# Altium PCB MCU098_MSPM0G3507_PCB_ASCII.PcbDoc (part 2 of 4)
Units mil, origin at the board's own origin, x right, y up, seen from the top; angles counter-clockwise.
Board outline 2310.03 x 4205.03 mil, 4 copper layers (Top Layer, VCC Layer, GND Layer, Bottom Layer), stack 62.4 mil thick; 260 components, 182 nets, 835 pads, 237 vias.
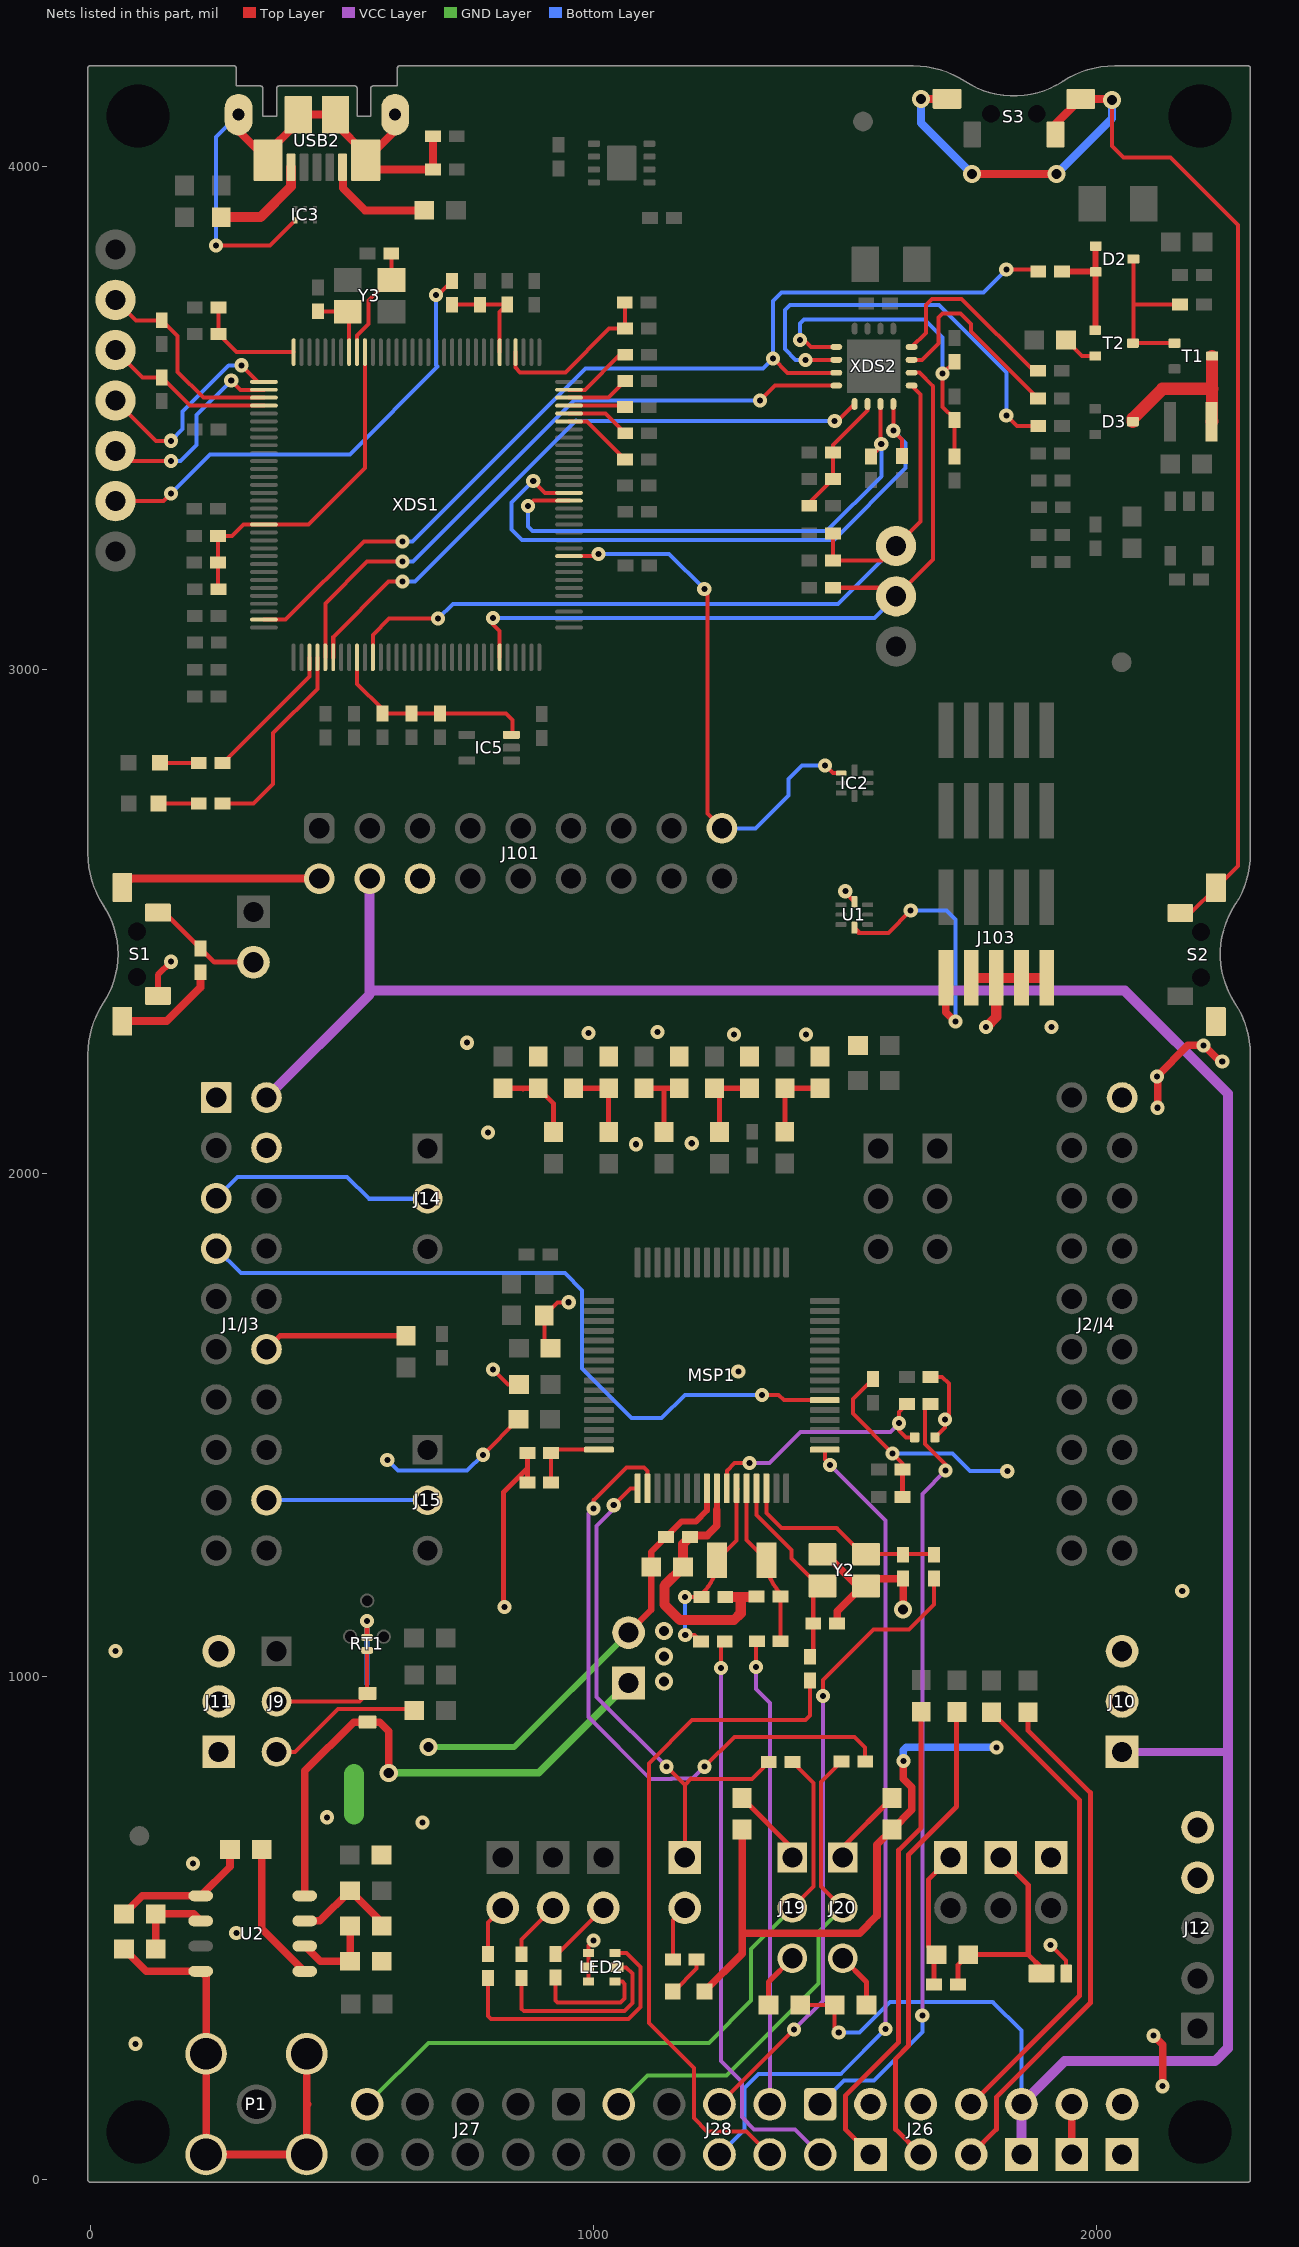
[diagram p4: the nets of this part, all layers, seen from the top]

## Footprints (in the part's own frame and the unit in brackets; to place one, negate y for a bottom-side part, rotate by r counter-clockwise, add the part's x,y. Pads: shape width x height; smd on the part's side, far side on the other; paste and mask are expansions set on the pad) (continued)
DCK0005A_N [mm] "SOT353, 5-Leads, Body 2x1.3mm, Pitch 0.65mm, Lead Span 2.1mm, IPC Medium Density"
  rrect25% 0.85x0.4 smd: 1(-1.125,0.65) 2(-1.125,0) 3(-1.125,-0.65) 4(1.125,-0.65) 5(1.125,0.65)
  silkscreen extent -1.48,-1.02 0.55,1.1
DEC0002A [mm] "X1SON-2"
  rrect57% 0.35x0.6 smd paste-0.5 mask+0: 1(-0.325,0) 2(0.325,0)
  rrect33% 0.3x0.5 on Top Paste: 1S(-0.35,0) 2S(0.35,0)
DRB0008A [mm] "VSON-8"
  rrect32% 0.6x0.31 smd: 1(-1.4,0.975) 2(-1.4,0.325) 3(-1.4,-0.325) 4(-1.4,-0.975) 5(1.4,-0.975) 6(1.4,-0.325) 7(1.4,0.325) 8(1.4,0.975)
  rrect7% 1.5x1.75 smd paste-0.75: 9(0,0)
  silkscreen extent -1.73,-1.73 1.73,1.73
DRY0006A [mm] "PSON, 6-Leads, Body 1x1.45mm, Pitch 0.5mm, TI Recommended"
  rect 0.35x0.2 smd: 1(-0.275,0.5)
  rect 0.3x0.2 smd: 2(-0.3,0) 3(-0.3,-0.5) 4(0.3,-0.5) 5(0.3,0) 6(0.3,0.5)
  silkscreen extent -0.5,-0.85 0.2,0.85
Epson_FC-135 [mm] "SMD, 2-Leads, Body 3.2x1.5mm"
  rect 1x1.8 smd: 1(-1.25,0) 2(1.25,0)
  silkscreen extent -0.35,-0.8 0.35,0.8
ERA3A [mm] "SMD, 2-Leads, Body 1.6x0.8mm"
  rrect15% 0.65x0.9 smd: 1(-0.725,0) 2(0.725,0)
ESD_Overlay_Large [mil]
  silkscreen extent -254,-219 250,219
FCC_disclaimer [mil]
Fiducial10-30 [mm]
  round 1 smd mask+0: 1(0,0)
  Top Layer keep-out circle w1.678: c0,0 r0.75
FP-ERA-2AEB104X_0402-MFG [mm]
  rrect21% 0.475x0.5 smd paste+0 mask+0: 1(-0.512,0) 2(0.512,0)
  silkscreen extent -0.5,-0.63 0.5,0.63
FP-VEMD4110X01_0805-MFG [mm]
  rrect17% 0.9x0.6 smd paste+0 mask+0: 1(0,-0.8)
  rrect11% 0.9x1.3 smd paste+0 mask+0: 2(0,0.45)
  silkscreen extent -0.85,-1.78 0.85,1.05
FP-X1E0000210179_TSX-3225-MFG [mm] "SMD, 4-Leads, Body 3.2x2.5mm"
  rrect9% 1.4x1.15 smd paste+0 mask+0: 1(-1.1,-0.8) 2(1.1,-0.8) 3(1.1,0.8) 4(-1.1,0.8)
  silkscreen extent -1.23,-2.05 0,1.33
Keystone5001 [mil] "For Keystone 500x miniature loop terminals"
  round 80 hole 40: 1(0,0)
  silkscreen extent -52,-52 52,52
KY_MAE-10 [mil] "Spacer Nylon Support"
LED_LTST-C190 [mm] "Lite-On"
  rect 0.8x0.8 smd: 1(-0.75,0) 2(0.75,0)
  silkscreen extent -1.1,-0.8 1.8,0.8
Molex_1051640001 [mm] "Receptacle, USB 2.0, Micro B, 5 Pos, 0.65mm Pitch, R/A, SMT"
  rrect22% 0.45x1.38 smd: 1(1.3,4.11) 2(0.65,4.11) 3(0,4.11) 4(-0.65,4.11) 5(-1.3,4.11)
  rrect7% 1.475x2.1 smd: 6(-2.462,3.75) 11(2.462,3.75)
  rrect100% 1.4x2.1 hole 0.6 slot 1.3 at 90 deg: 7(-3.95,1.45) 10(3.95,1.45)
  rrect7% 1.375x1.9 smd: 8(-0.937,1.45) 9(0.937,1.45)
  silkscreen extent 1.2,5.1 1.4,5.4
NDK_NX3225GA [mm] "NDK"
  rect 1.2x1.4 smd: 1(-0.8,1.1) 2(-0.8,-1.1) 3(0.8,-1.1) 4(0.8,1.1)
  silkscreen extent -1.9,-0.1 1.4,2
NPTH125mil [mil]
  round 120 hole 125 unplated mask+0: 1(0,0)
PDT0128A [mm] "Thin QFP, 128-Leads, Body 14x14mm, Pitch 0.4mm"
  oval 1.4x0.2 smd: 1(-7.7,6.2) 2(-7.7,5.8) 3(-7.7,5.4) 4(-7.7,5) 5(-7.7,4.6) 6(-7.7,4.2) 7(-7.7,3.8) 8(-7.7,3.4) 9(-7.7,3) 10(-7.7,2.6) 11(-7.7,2.2) 12(-7.7,1.8) 13(-7.7,1.4) 14(-7.7,1) 15(-7.7,0.6) 16(-7.7,0.2) 17(-7.7,-0.2) 18(-7.7,-0.6) 19(-7.7,-1) 20(-7.7,-1.4) 21(-7.7,-1.8) 22(-7.7,-2.2) 23(-7.7,-2.6) 24(-7.7,-3) 25(-7.7,-3.4) 26(-7.7,-3.8) 27(-7.7,-4.2) 28(-7.7,-4.6) 29(-7.7,-5) 30(-7.7,-5.4) 31(-7.7,-5.8) 32(-7.7,-6.2) 65(7.7,-6.2) 66(7.7,-5.8) 67(7.7,-5.4) 68(7.7,-5) 69(7.7,-4.6) 70(7.7,-4.2) 71(7.7,-3.8) 72(7.7,-3.4) 73(7.7,-3) 74(7.7,-2.6) 75(7.7,-2.2) 76(7.7,-1.8) 77(7.7,-1.4) 78(7.7,-1) 79(7.7,-0.6) 80(7.7,-0.2) 81(7.7,0.2) 82(7.7,0.6) 83(7.7,1) 84(7.7,1.4) 85(7.7,1.8) 86(7.7,2.2) 87(7.7,2.6) 88(7.7,3) 89(7.7,3.4) 90(7.7,3.8) 91(7.7,4.2) 92(7.7,4.6) 93(7.7,5) 94(7.7,5.4) 95(7.7,5.8) 96(7.7,6.2)
  oval 0.2x1.4 smd: 33(-6.2,-7.7) 34(-5.8,-7.7) 35(-5.4,-7.7) 36(-5,-7.7) 37(-4.6,-7.7) 38(-4.2,-7.7) 39(-3.8,-7.7) 40(-3.4,-7.7) 41(-3,-7.7) 42(-2.6,-7.7) 43(-2.2,-7.7) 44(-1.8,-7.7) 45(-1.4,-7.7) 46(-1,-7.7) 47(-0.6,-7.7) 48(-0.2,-7.7) 49(0.2,-7.7) 50(0.6,-7.7) 51(1,-7.7) 52(1.4,-7.7) 53(1.8,-7.7) 54(2.2,-7.7) 55(2.6,-7.7) 56(3,-7.7) 57(3.4,-7.7) 58(3.8,-7.7) 59(4.2,-7.7) 60(4.6,-7.7) 61(5,-7.7) 62(5.4,-7.7) 63(5.8,-7.7) 64(6.2,-7.7) 97(6.2,7.7) 98(5.8,7.7) 99(5.4,7.7) 100(5,7.7) 101(4.6,7.7) 102(4.2,7.7) 103(3.8,7.7) 104(3.4,7.7) 105(3,7.7) 106(2.6,7.7) 107(2.2,7.7) 108(1.8,7.7) 109(1.4,7.7) 110(1,7.7) 111(0.6,7.7) 112(0.2,7.7) 113(-0.2,7.7) 114(-0.6,7.7) 115(-1,7.7) 116(-1.4,7.7) 117(-1.8,7.7) 118(-2.2,7.7) 119(-2.6,7.7) 120(-3,7.7) 121(-3.4,7.7) 122(-3.8,7.7) 123(-4.2,7.7) 124(-4.6,7.7) 125(-5,7.7) 126(-5.4,7.7) 127(-5.8,7.7) 128(-6.2,7.7)
  silkscreen extent -7.7,-6.3 6.3,6.99
PEC03SAAN_Launchpad_3V3 [mm] "SULLINS"
  rect 1.65x1.65 hole 1.016: 1(-2.54,0)
  round 1.65 hole 1.016: 2(0,0) 3(2.54,0)
  silkscreen extent -3.81,-1.27 3.81,6.3
PEC03SAAN_Launchpad_5V0 [mm] "SULLINS"
  rect 1.65x1.65 hole 1.016: 1(-2.54,0)
  round 1.65 hole 1.016: 2(0,0) 3(2.54,0)
  silkscreen extent -3.81,-6.31 3.81,1.27
PM0064A-MFG [mm]
  rrect33% 1.5x0.3 smd paste+0 mask+0: 1(-5.7,3.75) 2(-5.7,3.25) 3(-5.7,2.75) 4(-5.7,2.25) 5(-5.7,1.75) 6(-5.7,1.25) 7(-5.7,0.75) 8(-5.7,0.25) 9(-5.7,-0.25) 10(-5.7,-0.75) 11(-5.7,-1.25) 12(-5.7,-1.75) 13(-5.7,-2.25) 14(-5.7,-2.75) 15(-5.7,-3.25) 16(-5.7,-3.75) 33(5.7,-3.75) 34(5.7,-3.25) 35(5.7,-2.75) 36(5.7,-2.25) 37(5.7,-1.75) 38(5.7,-1.25) 39(5.7,-0.75) 40(5.7,-0.25) 41(5.7,0.25) 42(5.7,0.75) 43(5.7,1.25) 44(5.7,1.75) 45(5.7,2.25) 46(5.7,2.75) 47(5.7,3.25) 48(5.7,3.75)
  rrect33% 0.3x1.5 smd paste+0 mask+0: 17(-3.75,-5.7) 18(-3.25,-5.7) 19(-2.75,-5.7) 20(-2.25,-5.7) 21(-1.75,-5.7) 22(-1.25,-5.7) 23(-0.75,-5.7) 24(-0.25,-5.7) 25(0.25,-5.7) 26(0.75,-5.7) 27(1.25,-5.7) 28(1.75,-5.7) 29(2.25,-5.7) 30(2.75,-5.7) 31(3.25,-5.7) 32(3.75,-5.7) 49(3.75,5.7) 50(3.25,5.7) 51(2.75,5.7) 52(2.25,5.7) 53(1.75,5.7) 54(1.25,5.7) 55(0.75,5.7) 56(0.25,5.7) 57(-0.25,5.7) 58(-0.75,5.7) 59(-1.25,5.7) 60(-1.75,5.7) 61(-2.25,5.7) 62(-2.75,5.7) 63(-3.25,5.7) 64(-3.75,5.7)
  silkscreen extent -7.12,-5.1 5.1,5.1
RSA0016B [mm] "QFN, 16-Leads, Body 4x4mm, Pitch 0.65mm, Thermal Pad 2.7x2.7mm, TI Recommended"
  oval 0.6x0.3 smd: 1(-1.9,0.975) 2(-1.9,0.325) 3(-1.9,-0.325) 4(-1.9,-0.975) 9(1.9,-0.975) 10(1.9,-0.325) 11(1.9,0.325) 12(1.9,0.975)
  oval 0.3x0.6 smd: 5(-0.975,-1.9) 6(-0.325,-1.9) 7(0.325,-1.9) 8(0.975,-1.9) 13(0.975,1.9) 14(0.325,1.9) 15(-0.325,1.9) 16(-0.975,1.9)
  rect 2.7x2.7 smd paste-1.35: 17(0,0)
  Top Layer keep-out region: -2,1.5 -1.5,1.5 -1.5,2 -2,2
  silkscreen extent -2.2,-2.2 2.2,2.2
RSE0008A [mm] "QFN, 8-Leads, Body 1.5x1.5mm, Pitch 0.5mm, TI Recommended"
  rrect40% 0.55x0.25 smd: 1(-0.675,0.5) 3(-0.675,-0.5) 5(0.675,-0.5) 7(0.675,0.5)
  rrect50% 0.55x0.2 smd: 2(-0.675,0) 6(0.675,0)
  rrect33% 0.3x0.6 smd: 4(0,-0.65) 8(0,0.65)
  silkscreen extent -1.02,-0.92 0.77,0.93
Samtec_FTSH-105-01-x-DV-K [mm] "Header(Shrouded), 1.27mm, 5x2, SMT"
  rect 2.79x0.74 smd: 1(-2.035,2.54) 2(2.035,2.54) 3(-2.035,1.27) 4(2.035,1.27) 5(-2.035,0) 6(2.035,0) 7(-2.035,-1.27) 8(2.035,-1.27) 9(-2.035,-2.54) 10(2.035,-2.54)
  silkscreen extent -3.73,-3.48 3.73,3.48
Samtec_HTSW-105-07-G-S [mm] "Samtec 100mil, 1x5, 230 mil above insulator"
  rrect6% 1.65x1.65 hole 1.016: 1(-5.08,0)
  round 1.65 hole 1.016: 2(-2.54,0) 3(0,0) 4(2.54,0) 5(5.08,0)
  silkscreen extent -7.11,-1.27 6.35,1.27
SNT-100-BK-G [mil] "Samtec STEP model"
  round 1 on Mech3: 0(0,0)
SOT-323 [mm] "Diodes Inc recommended land pattern.  2016-02-24"
  rrect21% 0.6x0.47 smd: 1(-0.95,0.65) 2(-0.95,-0.65) 3(0.95,0)
  silkscreen extent -1.14,-1.22 0.77,1.22
Sullins_PBC03DAAN [mm] "Sullins 100mil, 2x3, 230 mil above insulator"
  rect 1.65x1.65 hole 1.016: 1(-1.27,2.54)
  round 1.65 hole 1.016: 2(1.27,2.54) 3(-1.27,0) 4(1.27,0) 5(-1.27,-2.54) 6(1.27,-2.54)
  silkscreen extent -2.67,-3.81 2.54,4.58
Sullins_PxC09DAAN [mm] "Header, 2.54mm, 9x2, TH"
  rrect50% 1.55x1.55 hole 1.02: 1(-1.27,-10.16)
  round 1.55 hole 1.02: 2(1.27,-10.16) 3(-1.27,-7.62) 4(1.27,-7.62) 5(-1.27,-5.08) 6(1.27,-5.08) 7(-1.27,-2.54) 8(1.27,-2.54) 9(-1.27,0) 10(1.27,0) 11(-1.27,2.54) 12(1.27,2.54) 13(-1.27,5.08) 14(1.27,5.08) 15(-1.27,7.62) 16(1.27,7.62) 17(-1.27,10.16) 18(1.27,10.16)
  silkscreen extent -2.95,-11.43 2.54,11.43
SW_1188E [mm] "SMD, 4-Leads, Body 7.8x3.5mm"
  rrect10% 1x1.45 smd: 1(-1.1,3.375) 2(-1.1,-3.375)
  rrect11% 1.3x0.9 smd: 3(0.7,2.1) 4(0.7,-2.1)
  round 0 hole 0.9 unplated: ""(-0.35,-1.15) ""(-0.35,1.15)
  silkscreen extent -1.97,-2.28 0.95,2.28
TE_5-1814832-1 [mm] "SMA Straight PCB Socket Die Cast, TH"
  round 2 hole 1.5: 1(0,0)
  round 2.1 hole 1.6: 2(-2.54,2.54) 3(-2.54,-2.54) 4(2.54,-2.54) 5(2.54,2.54)
  silkscreen extent -3.2,-3.2 3.2,3.2
TI_Horizontal_Overlay_Medium [mil]
TI_Horizontal_Overlay_Small [mil]
WEEE_Minimum [mil] "WEEElie bin"
  silkscreen extent 22,-71 54,74
WURTH_61301021121 [mm] "Header, 2.54mm, 5x2, TH"
  rrect25% 1.65x1.65 hole 1.15: 1(-5.08,-1.27)
  round 1.65 hole 1.15: 2(-5.08,1.27) 3(-2.54,-1.27) 4(-2.54,1.27) 5(0,-1.27) 6(0,1.27) 7(2.54,-1.27) 8(2.54,1.27) 9(5.08,-1.27) 10(5.08,1.27)
  silkscreen extent -6.35,-2.9 6.35,2.54

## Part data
C1: library part CMP-0007304-1, "CAP, CERM, 10 uF, 6.3 V, +/- 20%, X5R, 0603"
C2 C4: library part CMP-0006614-2, "CAP, CERM, 0.1 uF, 50 V, +/- 20%, X5R, 0402"
C3: library part CMP-0006551-2, "CAP, CERM, 0.47 uF, 6.3 V, +/- 10%, X5R, 0402"
C5: library part CMP-0006388-2, "CAP, CERM, 47 pF, 25 V, +/- 5%, C0G/NP0, 0402"
C6: library part CMP-0006590-2, "CAP, CERM, 0.01 uF, 16 V, +/- 10%, X5R, 0402"
C7 C8: library part CMP-0007006-5, "CAP, CERM, 1 uF, 25 V, +/- 10%, X5R, 0603"
C9 C10 C11 C12: library part CMP-0006439-2, "CAP, CERM, 22 pF, 50 V, +/- 5%, C0G/NP0, 0402"
C13 C17 C18 C20 C24 C27 C28 C33 C38 C39 C44: library part CMP-0006623-2, "CAP, CERM, 0.1 uF, 6.3 V, +/- 10%, X7R, 0402"
C14 C15 C16 C22 C26: library part CMP-0006658-2, "CAP, CERM, 0.01 uF, 25 V, +/- 10%, X7R, 0402"
C19 C21 C25 C55: library part CMP-0006276-2, "CAP, CERM, 1 uF, 25 V, +/- 10%, X5R, 0402"
C23 C56: library part CMP-0006543-2, "CAP, CERM, 2.2 uF, 6.3 V, +/- 10%, X5R, 0402"
C29 C30: library part CMP-0006415-2, "CAP, CERM, 12 pF, 50 V, +/- 5%, C0G/NP0, 0402"
C31 C34: library part CMP-0006454-1, "CAP, CERM, 33 pF, 50 V, +/- 5%, C0G/NP0, 0402"
C32 C36: library part CMP-0011480-1, "CAP, TA, 4.7 uF, 16 V, +/- 10%, 4 ohm, SMD"
C35: library part CMP-0006354-2, "CAP, CERM, 1000 pF, 50 V, +/- 10%, X7R, AEC-Q200 Grade 1, 0402"
C37 C43: library part CMP-0007341-4, "CAP, CERM, 4.7 uF, 16 V, +/- 10%, X5R, 0603"
C40: library part CMP-0007313-1, "CAP, CERM, 47 uF, 6.3 V, +/- 20%, X5R, 0603"
C41 C42: library part CMP-0006648-1, "CAP, CERM, 0.22 uF, 16 V, +/- 10%, X7R, 0402"
C45 C46 C48 C49 C50 C51 C52 C53: library part CMP-0006906-5, "CAP, CERM, 2.2 uF, 10 V, +/- 10%, X5R, 0603"
C47: library part CMP-0006970-1, "CAP, CERM, 82 pF, 50 V, +/- 10%, C0G/NP0, 0603"
C54: library part CMP-0006688-2, "CAP, CERM, 3300 pF, 50 V, +/- 10%, X7R, 0402"
D1: library part CMP-0093192-1, "Photodiode PIN Chip 910nm Automotive 2-Pin Case 0805(2012Metric) T/R"
D2 D3: library part CMP-0028883-1, "Diode, Schottky, 40 V, 0.12 A, AEC-Q101, SOT-323"
FID1 FID2 FID3: library part CMP-0077181-1, "Fiducial mark.  There is nothing to buy or mount."
H1 H2: library part CMP-0077978-1, "Spacer Support, Nylon 66"
IC1: library part CMP-0074212-1, "2.7-4V Dual In/Single Out MOSFET, 0.5A Main/0.1A Aux Input, Act-Low Enable, Comm. Temp., DBV0005A (SOT-23-5)"
IC2 U1: library part CMP-0043125-2, "Low-Capacitance + / - 15 kV ESD Protection Array for High-Speed Data Interfaces, 6 Channels, -40 to +85 degC, 8-pin UQFN (RSE), Green (RoHS & no Sb/Br)"
IC3: library part CMP-0043115-1, "ESD-Protection Array for High-Speed Data Interfaces, 4 Channels, -40 to +85 degC, 6-pin SON (DRY), Green (RoHS & no Sb/Br)"
IC4: library part CMP-0036329-3, "500mA, Adjustable, Low Quiescent Current, Low-Noise, High-PSRR, Single-Output LDO Regulator, DRB0008A (VSON-8)"
IC5: library part CMP-0032790-2, "Precision Micropower Shunt Voltage Reference, 0.5% accuracy, 2.5 V, 15 ppm / degC, 15 mA, -40 to 85 degC, 5-pin SC70 (DCK), Green (RoHS & no Sb/Br)"
J1/J3: library part CMP-0003837-4, "Receptacle, 2.54mm, 10x2, Tin, TH"
J2/J4: library part CMP-0078266-4, "Receptacle, 2.54mm, 10x2, Tin, TH"
J4 J5 J6 J7 J8 J13 J16 J17 J18 J23 J24 J25: library part CMP-0055312-1, "Header, 100mil, 2x1, Tin, TH"
J9 J10 J11 J14 J15 J19 J20 J21 J22: library part CMP-0002338-1, "Header, 100mil, 3x1, Tin, TH"
J12: library part CMP-0075485-1, "Header, 100mil, 5x1, Gold, TH"
J26: library part CMP-0054565-2, "Header, 100mil, 3x2, Gold, TH"
J27 J28: library part CMP-0054806-2, "Header, 2.54 mm, 5x2, Gold, TH"
J101: library part CMP-0054622-1, "Header, 2.54mm, 9x2, Tin, TH"
J102 J103: library part CMP-0075634-1, "Header(Shrouded), 1.27mm, 5x2, Gold, SMT"
L1: library part CMP-0059590-1, "Inductor, Wirewound, Ceramic, 2.2 uH, 0.89 A, 0.13 ohm, SMD"
LED1 LED101: library part CMP-0002972-3, "LED, Red, SMD"
LED2: library part CMP-0074720-1, "LED, RGB, SMD"
LED102: library part CMP-0002827-3, "LED, Green, SMD"
LOGO1: library part CMP-0074844-1
Logo2 Logo3: library part CMP-0074838-1, "Texas Instrument Corporate Signature"
Logo4: library part CMP-0074840-1, "ESD Susceptible Symbol"
Logo6: library part CMP-0074847-1, "FCC_disclaimer"
Logo7: library part CMP-0074769-1
MH1 MH2 MH3 MH4: library part CMP-0078424-2, "PCB Mounting Hole, No Pad"
MSP1: library part CMP-0093960-1, "Mixed-Signal Microcontrollers With CAN-FD Interface LQFP64"
P1: library part CMP-0054990-1, "SMA Straight PCB Socket Die Cast, 50 Ohm, TH"
R1: library part CMP-0022292-1, "RES, 2.37 M, 1%, 0.1 W, 0603"
R2 R14: library part CMP-0026935-1, "RES, 47 k, 5%, 0.063 W, 0402"
R3 R52 R55 R57 R58 R61 R62 R63 R64 R65 R66 R67 R68 R69 R70 R71 R73 R74 R75 R76 R77 R78 R79 R80 R81 R82 R83 R84 R86 R89: library part CMP-0025885-5, "RES, 0, 5%, 0.1 W, 0603"
R4 R29 R30: library part CMP-0026934-2, "RES, 470, 5%, 0.063 W, 0402"
R5: library part CMP-0026878-1, "RES, 220, 5%, 0.063 W, 0402"
R6 R7: library part CMP-0026906-1, "RES, 330, 5%, 0.063 W, 0402"
R8: library part CMP-0088648-1, "Res Thin Film 0402 100K Ohm 0.1% 1/16W ±25ppm/°C Molded SMD SMD Punched Carrier T/R"
R9 R10 R11 R15 R17 R20 R22 R23: library part CMP-0027004-2, "RES, 0, 5%, 0.063 W, 0402"
R12 R16: library part CMP-0025927-5, "RES, 4.7 k, 5%, 0.1 W, 0603"
R13 R19: library part CMP-0026886-1, "RES, 270, 5%, 0.063 W, 0402"
R18 R21: library part CMP-0025906-5, "RES, 2.2 k, 5%, 0.1 W, 0603"
R24 R25 R26 R27 R34: library part CMP-0026852-1, "RES, 1.0 k, 5%, 0.063 W, 0402"
R28: library part CMP-0026824-3, "RES, 100, 5%, 0.063 W, AEC-Q200 Grade 0, 0402"
R31 R91 R92: library part CMP-0026825-4, "RES, 10 k, 5%, 0.063 W, 0402"
R32: library part CMP-0026413-2, "RES, 4.87 k, 1%, 0.063 W, AEC-Q200 Grade 0, 0402"
R33: library part CMP-0026824-1, "RES, 100, 5%, 0.063 W, 0402"
R35: library part CMP-0026946-3, "RES, 51, 5%, 0.063 W, AEC-Q200 Grade 0, 0402"
R36 R37 R43 R44 R50 R51 R53 R54 R88: library part CMP-0026728-1, "RES, 220 k, 1%, 0.0625 W, 0402"
R38 R85: library part CMP-0026695-1, "RES, 3.30 k, 1%, 0.1 W, AEC-Q200 Grade 0, 0402"
R39: library part CMP-0026231-1, "RES, 2.20 k, 1%, 0.063 W, 0402"
R40: library part CMP-0026517-1, "RES, 6.81 k, 1%, 0.063 W, 0402"
R41 R42: library part CMP-0026938-1, "RES, 4.7 k, 5%, 0.063 W, 0402"
R45 R46 R49: library part CMP-0026737-1, "RES, 47.0 k, 1%, 0.0625 W, 0402"
R47: library part CMP-0026743-1, "RES, 820, 1%, 0.063 W, 0402"
R48: library part CMP-0026934-1, "RES, 470, 5%, 0.063 W, 0402"
R56: library part CMP-0080084-1, "RES, 10.0 k, 0.1%, 0.1 W, AEC-Q200 Grade 0, 1.6x0.8mm"
R59 R60: library part CMP-0026938-5, "RES, 4.7 k, 5%, 0.063 W, AEC-Q200 Grade 0, 0402"
R72: library part CMP-0022736-4, "RES, 100, 1%, 0.1 W, 0603"
R87: library part CMP-0026731-1, "RES, 330 k, 1%, 0.0625 W, 0402"
R90: library part CMP-0026100-1, "RES, 1.00 M, 1%, 0.063 W, 0402"
RT1: library part CMP-0084565-1, "Thermistor, DEC0002A (X1SON-2)"
S1 S2 S3: library part CMP-0002328-1, "Switch, SPST, 0.05 A, 12 VDC, SMD"
SH-J1 SH-J2 SH-J3 SH-J4 SH-J5 SH-J6 SH-J7 SH-J8 SH-J9 SH-J10 SH-J11 SH-J12 SH-J13 SH-J14 SH-J15 SH-J16 SH-J17 SH-J18 SH-J19 SH-J20 SH-J21 SH-J22 SH-J23 SH-J24 SH-J25: library part CMP-0003623-3, "Shunt, 100mil, Gold plated, Black"
T1: library part CMP-0000035-1, "MOSFET, P-CH, -20 V, -0.82 A, SOT-323"
T2: library part CMP-0000466-1, "Transistor, NPN, 45 V, 0.1 A, SOT-323"
TP1 TP2 TP3 TP4 TP5 TP6 TP7 TP8 TP9 TP10: library part CMP-0055138-1, "Test Point, Miniature, Black, TH"
U2: library part CMP-0040798-2, "50 MHz, Low-Noise Single-Supply Rail-to-Rail Operational Amplifier, 2.2 to 5.5 V, -40 to 125 degC, 8-pin SOIC (D8), Green (RoHS & no Sb/Br)"
USB2: library part CMP-0055311-1, "Receptacle, USB 2.0, Micro B, 5 Position, R/A, SMT"
XDS1: library part CMP-0077954-1, "MSP432E401YTPDT, PDT0128A (TQFP-128)"
XDS2: library part CMP-0039611-2, "MSP430G2x52, MSP430G2x12 Mixed Signal Microcontroller, RSA0016B (VQFN-16)"
Y1: library part CMP-0004693-2, "Crystal, 32.768 KHz, 12.5 pF, SMD"
Y2: library part CMP-0098168-2, "Crystal 40MHz ±10ppm (Tol) ±20ppm (Stability) 12pF FUND 40Ohm 4-Pin Mini-CSMD T/R"
Y3: library part CMP-0004635-1, "Crystal, 16 MHz, 8pF, SMD"
ZZ2 ZZ3 ZZ4: library part AssemblyNote

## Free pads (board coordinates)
  round 0 hole 21 slot 162 at 90 deg unplated: 1(516,1079.25) 1(583,1079)
  round 0 hole 21 slot 87 at 0 deg unplated: 1(550,1150.56)

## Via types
v1: diameter 28, hole 12, Top Layer to Bottom Layer, 211 vias
v2: diameter 36, hole 20, Top Layer to Bottom Layer, 17 vias
v3: diameter 19.68, hole 7.87, Top Layer to Bottom Layer, 9 vias

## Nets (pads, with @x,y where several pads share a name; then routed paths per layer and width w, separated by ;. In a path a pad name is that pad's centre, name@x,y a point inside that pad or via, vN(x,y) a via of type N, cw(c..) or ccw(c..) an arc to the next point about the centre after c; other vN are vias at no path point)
3.3VM: J13.1 R56.2 U2.8 | length 1096
  Top Layer w15: U2.8@426.01,563.99 426.01,812.06 523.15,909.21 R56.2@551,909.21 574.87,909.21 592.88,891.2 v2(592.88,808.35)
  GND Layer w15: v2(592.88,808.35) 890.72,808.35 J13.1@1069.38,987
3V3: C1.1 C2.1 J1/J3.1 J11.1 J12.4 J13.2 J25.1 J25.2 J101.6 J103.1 LED1.1 MSP1.40 R2.2 R18.2 R21.2 R59.1 R60.1 R66.1 S1.4 U1.8 | length 3942.6
  Top Layer w8: v1(779.81,1440.28) R66.1@850.5,1511 ; LED1.1@1218.31,374 LED1.1@1219.3,374.98 ; U1.8@1517.93,2487.9 1525.82,2480 1525.82,2477.01 1585.51,2477.01 v1(1630,2521.5) ; R2.2@1555,1591 1514.9,1550.9 1514.9,1522.1 v1(1594,1443) 1613.62,1423.38 R60.1@1613.62,1410.66
  Top Layer w10: R59.1@1613.62,1356.35 R60.1@1613.62,1410.66
  Top Layer w12: S1.4@134.34,2352.05 134.34,2393.76 v1(160.5,2419.92) ; J13.2@1069.38,1087 1114.5,1132.13 C1.1@1114.5,1217 1114.5,1247.47 C2.1@1144.03,1277 1175.03,1308 1203.65,1308 1225.16,1329.5 MSP1.40@1225.16,1373.59
  Top Layer w15: LED1.1@1220.28,374 1295,448.72 1295,490 ; R18.2@1295,695.5 1295,490 ; v1(1615.38,831.7) 1615.38,796.62 1632.2,779.8 1632.2,734.7 R21.2@1593,695.5 1563,665.5 1563,524 1529,490 1295,490 ; J103.1@1700,2387.88 1700,2320 v1(1719,2301) ; J25.1@1950,50 J25.2@1950,150 ; v1(2112.5,286) 2130.5,268 v1(2130.5,185.66) ; v1(2120.5,2129.75) 2120.5,2191.25 v1(2119.5,2192.25) 2180.78,2253.53 v1(2212.05,2253.53) 2243.59,2222 v1(2249,2222)
  GND Layer w12: v2(671.62,859.36) 841.74,859.36 J13.2@1069.38,1087
  Bottom Layer w8: v1(590,1429.73) 611.14,1408.59 748.12,1408.59 v1(779.81,1440.28) ; v1(1594,1443) 1712.61,1443 1747.97,1407.63 v1(1821.89,1407.63) ; v1(1630,2521.5) 1701.5,2521.5 1719,2504 v1(1719,2301)
  Bottom Layer w15: v1(1615.38,831.7) 1615.38,853.07 1621.31,859 v1(1800.45,859)
+5V: J1/J3.21 J10.1 J23.1 J23.2 J101.4 R12.2 R16.2 | length 5658.7
  Top Layer w8: R12.2@1410.5,347 R16.2@1479,347 1479,300 v1(1487,292)
  VCC Layer w16: J10.1@2050,850 2259,850 2260,849 ; 2259.28,552.72 2260,552
  VCC Layer w20: J1/J3.21@350,2150 555,2355 555,2362.49 ; J101.4@555,2585 555,2362.49 ; J23.1@1850,50 J23.2@1850,150 1936,236 2235,236 2260,261 2260,552 2260,849 2260,2158 2055.51,2362.49 555,2362.49
  Bottom Layer w8: v1(1487,292) 1528,292 1589,353 1793,353 1850,296 J23.2@1850,150
AVCCOUT: C31.1 R36.1 R37.2 XDS2.1 | length 692.2
  Top Layer w8: v1(1410,3655) 1418.48,3655 1432.09,3641.39 XDS2.1@1482.2,3641.39 ; R36.1@1717,3423.62 R37.2@1717,3496 1717,3498.89 1693.32,3522.58 v1(1693.32,3588.31) C31.1@1717,3612
  Bottom Layer w8: v1(1410,3655) 1410,3688 1418,3696 1657.64,3696 1693.32,3660.32 v1(1693.32,3588.31)
BSL_INVOKE: IC2.1 J101.17 XDS1.42 | length 1103.5
  Top Layer w8: XDS1.42@951.15,3225.64 1005.39,3225.64 v1(1009.88,3230.13) ; v1(1219.88,3160.34) 1225.91,3154.31 1225.91,2714.09 J101.17@1255,2685 ; v1(1460.08,2810) 1475.52,2794.56 IC2.1@1491.99,2794.56
  Bottom Layer w8: v1(1009.88,3230.13) 1150.09,3230.13 v1(1219.88,3160.34) ; J101.17@1255,2685 1321.53,2685 1387,2750.47 1387,2782.76 1414.24,2810 v1(1460.08,2810)
CANRX: J26.3 R65.1 | length 950.4
  Top Layer w10: J26.3@1650,50 1600,100 1600,240 1625.8,265.8 1625.8,645.8 1721,741 1721,928.42 R65.1@1721.84,929.25
CANTX: J26.1 R64.1 | length 975.9
  Top Layer w10: J26.1@1563,50 J26.1@1550,50 1500,100 1500,167 1606.03,273.03 1606.03,654.6 1650.84,699.4 R64.1@1650.84,929.76
DCDCCAL0: R39.1 XDS2.12 | length 382.2
  Top Layer w8: XDS2.12@1631.8,3641.39 1660,3669.58 1660,3725 1672,3737 1731,3737 1873.8,3594.2 R39.1@1882.76,3594.2
DCDCCAL1: R38.1 XDS2.2 | length 846.7
  Top Layer w8: v1(1421.09,3615.8) XDS2.2@1482.2,3615.8 ; v1(1819.88,3505) 1840.88,3484 R38.1@1883.38,3484
  Bottom Layer w8: v1(1421.09,3615.8) 1401.2,3615.8 1380.01,3636.99 1380.01,3715.01 1390,3725 1685.86,3725 1819.88,3590.97 v1(1819.88,3505)
DCDCCAL2: R40.1 XDS2.11 | length 398.5
  Top Layer w8: XDS2.11@1631.8,3615.8 1652.8,3615.8 1685,3648 1685,3700 1693,3708 1729,3708 1750,3687 1750,3671.76 R40.1@1882.76,3539
DCDCIO0: XDS1.5 XDS2.4 | length 1301.6
  Top Layer w8: XDS1.5@466.9,3024.85 466.9,3131.9 550,3215 v1(620,3215) ; v1(1330.35,3535) 1359.97,3564.61 XDS2.4@1482.2,3564.61
  Bottom Layer w8: v1(620,3215) 641.3,3215 961.3,3535 v1(1330.35,3535)
DCDCIO1: XDS1.6 XDS2.5 | length 1268.8
  Top Layer w8: XDS1.6@482.65,3024.85 482.65,3065.15 ; 482.77,3065.15 482.77,3065.27 592.5,3175 v1(620,3175) ; v1(1479,3494) 1484.42,3494 XDS2.5@1518.61,3528.2
  Bottom Layer w8: v1(620,3175) 645,3175 965,3495 966,3494 v1(1479,3494)
DCDCPULSE: R47.2 XDS1.127 XDS2.3 | length 2033.7
  Top Layer w8: XDS1.127@344.85,3099.65 388.15,3099.65 543.5,3255 v1(620,3255) ; v1@1356,3619 1385.08,3589.92 1481.91,3589.92 XDS2.3@1482.2,3590.2 ; v1(1819.88,3795) 1879.38,3795 R47.2@1883.38,3791
  Bottom Layer w8: v1(620,3255) 640,3255 984,3599 1336.53,3599 v1(1356,3618.47) 1356,3733 1373,3750 1774.88,3750 v1(1819.88,3795)
DCDCRST: C35.1 R45.1 TP1.1 XDS1.11 XDS2.9 | length 1694.9
  Top Layer w8: XDS1.11@561.39,3024.85 561.39,3069.39 593.5,3101.5 v1(691,3101.5) ; R45.1@1475.62,3271 C35.1@1475.62,3217 1572,3217 TP1.1@1601,3246 1649.75,3294.75 1649.75,3546.66 XDS2.9@1631.8,3564.61
  Bottom Layer w8: v1(691,3101.5) 720.4,3130.9 1485.9,3130.9 TP1.1@1601,3246
DCDCTEST: R46.2 TP3.1 XDS1.27 XDS2.10 | length 1535.8
  Top Layer w8: v1(800,3103) 800,3090.3 813.35,3076.95 XDS1.27@813.35,3024.85 ; R46.2@1475.62,3163 1584,3163 TP3.1@1601,3146 1674,3219 1674,3563.34 1647.13,3590.2 XDS2.10@1631.8,3590.2
  Bottom Layer w8: v1(800,3103) 1558,3103 TP3.1@1601,3146
GND: C1.2 C2.2 C3.2 C4.2 C6.2 C7.2 C9.1 C10.1 C11.1 C12.1 C45.2 C47.2 C48.2 C49.2 C50.2 C51.2 C52.2 D1.1 J1/J3.22 J2/J4.20 J10.2 J10.3 J11.2 J11.3 J12.5 J18.1 J24.1 J24.2 J26.2 J26.4 J101.2 J103.3 J103.5 J103.7 J103.9 LED2.1 LED2.2 LED2.3 MSP1.41 P1.2 P1.3 P1.4 P1.5 R3.1 R8.2 R14.1 R67.1 R68.1 R70.1 RT1.1 S1.1 S1.2 S2.1 S2.2 S2.4 S3.1 S3.2 S3.3 U1.4 U2.4 Y2.2 Y2.4 | length 6449.1
  Top Layer w8: v1(800,1610.07) 830.07,1580 R67.1@851.5,1580 ; C7.2@914.5,1652 902,1664.5 R3.1@902,1716.85 928.45,1743.3 v1(950.5,1743.3) ; LED2.3@989.43,393.46 LED2.1@989.43,450.54 989.43,464.97 v1(1000,475.54) ; v1(1500,2560) 1500,2557.01 U1.4@1517.93,2539.08 ; C6.2@1669.62,1595 1692.44,1595 1706,1581.44 1706,1518 v1(1698,1510) 1698,1494.82 R8.2@1678.18,1475 ; v1(1908,466) 1939,435 D1.1@1939,409.52 ; v2(2030,4132) 2030,4041 2053.13,4017.87 2146.29,4017.87 2280,3884.17 2280,2610.57 S2.2@2236.31,2566.87 2186.11,2516.68 S2.4@2165.44,2516.68
  Top Layer w10: RT1.1@550,1077.3 v1(550,1109.72) ; v1(823.03,1138) 821,1140.03 821,1365.84 868.38,1413.21 ; C3.2@868.38,1385.27 868.38,1413.21 ; C4.2@868.38,1444 868.38,1413.21
  Top Layer w12: 1244.84,1330.57 MSP1.41@1244.84,1373.59
  Top Layer w15: R70.1@67.02,457.99 111.02,413.99 U2.4@219.32,413.99 230,403.31 P1.2@230,250 P1.3@230,50 P1.4@430,50 430,147.97 ; P1.5@430,250 430,147.97 ; 432.03,150 430,147.97 ; C2.2@1191.28,1277 1191.28,1279.93 1225.93,1279.93 1244.84,1298.84 1244.84,1330.57 ; Y2.2@1448.05,1243.5 1460.5,1243.5 1523.5,1180.5 Y2.4@1534.66,1180.5 ; C10.1@1483.62,1105 1483.62,1129.46 Y2.4@1534.66,1180.5 ; v2(1615,1133) C12.1@1615,1194.38 1548.54,1194.38 Y2.4@1534.66,1180.5
  Top Layer w16: S1.2@63.47,2301.85 151.8,2301.85 219,2369.05 R14.1@219,2399 ; S1.1@63.47,2567.6 80.87,2585 J101.2@455,2585 ; v2(1650.69,4134.31) S3.2@1702.13,4134.31 ; v2@1752.32,3985.32 v2(1752,3985) v2(1920,3985) ; S3.3@1920,4061.12 S3.3@1917.68,4063.44 1917.68,4084.11 S3.1@1967.87,4134.31 v2@2030,4134.31
  Top Layer w20: C2.2@1191.28,1277 1177.5,1263.22 C1.2@1177.5,1217 1140.45,1179.95 1140.45,1142.82 1171.27,1112 1279,1112 1292.34,1125.34 1292.34,1158 ; C9.1@1261.62,1158 1292.34,1158 ; C11.1@1323.72,1158.65 1323.07,1158 1292.34,1158 ; J103.3@1750,2387.88 J103.5@1800,2387.88 ; v1(1779.88,2289.97) 1800,2310.09 J103.5@1800,2387.88 ; J103.9@1900,2387.88 J103.7@1850,2387.88 J103.5@1800,2387.88
  GND Layer w40: 523.59,805.5 524,726
  Bottom Layer w10: 550,984.75 v1(550,1109.72)
  Bottom Layer w16: v2(1650.69,4134.31) 1650.69,4086.31 v2(1752,3985) ; v2(1920,3985) 2030,4095 v2(2030,4132)
  other v1: 89.87,270 290,490.19 204.02,628 660,710.04 470.5,720 50,1050.25 2169.5,1170 1287.41,1606 1084.35,2057.25 1194.92,2059.25 789.77,2080.75 748.04,2259 1279.3,2275 1422.24,2275 990,2278 1126.96,2280.64 1909.91,2290
  other v2: 1140,989.5 1140,1039.75 1140,1090
HOSTSCL: R42.1 XDS1.49 XDS2.7 | length 1051.7
  Top Layer w8: v1(870,3325.09) 880.78,3335.87 XDS1.49@951.15,3335.87 ; R42.1@1551,3423.98 1569.8,3442.77 XDS2.7@1569.8,3528.2
  Bottom Layer w8: v1(870,3325.09) 870,3285 879,3276 1463,3276 1571.5,3384.5 v1(1571.5,3448.35)
HOSTSDA: R41.1 XDS1.50 XDS2.8 | length 1241.2
  Top Layer w8: v1(880,3375.35) 903.73,3351.62 XDS1.50@951.15,3351.62 ; XDS2.8@1595.39,3528.2 v1(1595.39,3475) 1613,3457.39 R41.1@1613,3424.62
  Bottom Layer w8: v1(880,3375.35) 837.08,3332.44 837.08,3278.92 858,3258 1477.15,3258 1620.02,3400.87 1620.02,3450.37 v1(1595.39,3475)
IRSTN: R33.1 TP9.1 | length 937.9
  Top Layer w8: TP9.1@50,3335 145,3335 v1(160,3350) ; v1(687,3745) 691.24,3745 R33.1@718.87,3772.62
  Bottom Layer w8: v1(160,3350) 238,3428 515.62,3428 690,3602.38 687,3605.38 v1(687,3745)
ITCK: R92.2 TP6.1 XDS1.100 | length 340.5
  Top Layer w8: TP6.1@50,3635 104,3581 R92.2@142,3581 198.15,3524.85 XDS1.100@344.85,3524.85
ITDI: TP8.1 XDS1.98 | length 411.7
  Top Layer w8: TP8.1@50,3435 70,3415 v1(160,3415) ; v1(280,3575) 298.65,3556.35 XDS1.98@344.85,3556.35
  Bottom Layer w8: v1(160,3415) 179,3415 211,3447 211,3506 v1(280,3575)
ITDO: TP7.1 XDS1.97 | length 424.3
  Top Layer w8: TP7.1@50,3535 130,3455 v1(160,3455) ; v1(300,3605) 332.91,3572.09 XDS1.97@344.85,3572.09
  Bottom Layer w8: v1(160,3455) 183,3478 183,3513 275,3605 v1(300,3605)
ITMS: R91.2 TP5.1 XDS1.99 | length 417.2
  Top Layer w8: TP5.1@50,3735 90.62,3694.38 R91.2@142,3694.38 173,3663.38 173,3592 224.4,3540.6 XDS1.99@344.85,3540.6
LINRX: J26.6 R63.1 | length 945.4
  Top Layer w10: J26.6@1750,150 1965,365 1965,754.59 R63.1@1790.84,928.76 R63.1@1787,924.92
LINTX: J26.5 R62.1 | length 1029.5
  Top Layer w10: J26.5@1750,50 1800,100 1800,164 1987,351 1987,768.73 1862.84,892.9 R62.1@1862.84,928.76 R62.1@1862,927.92
NetC3_1: C3.1 C4.1 MSP1.32 | length 156.3
  Top Layer w8: C3.1@915.62,1385.27 C4.1@915.62,1444 921.98,1450.36 MSP1.32@1010.59,1450.36
NetC5_1: C5.1 J16.1 R1.2 | length 279.6
  Top Layer w10: C5.1@1676.38,387.54 1676.38,441.87 R1.2@1681.5,447 1665,463.5 1665,596 J16.1@1709,640
NetC5_2: C5.2 D1.2 J17.1 R1.1 | length 451.1
  Top Layer w10: C5.2@1723.62,387.54 1723.62,426.13 R1.1@1744.5,447 1863.53,447 ; J17.1@1809,640 1863.53,585.47 1863.53,447 ; D1.2@1889.79,409.52 1889.79,420.74 1863.53,447
NetC13_1: C13.1 R28.2 XDS1.96 | length 217.1
  Top Layer w8: R28.2@254.62,3720 C13.1@254.62,3667 290.47,3631.15 XDS1.96@403.91,3631.15
NetC20_1: C20.1 R31.1 R33.2 XDS1.70 | length 209.4
  Top Layer w8: R33.2@718.87,3725.38 828,3725.38 813.35,3710.73 XDS1.70@813.35,3631.15
NetC23_1: C23.1 C24.1 C25.1 XDS1.87 XDS1.115 | length 684.7
  Top Layer w8: C25.1@254.62,3160 253.62,3161 C24.1@253.62,3213 C23.1@253.62,3266 281.37,3266 304,3288.63 XDS1.115@344.85,3288.63 433.63,3288.63 545.64,3400.64 XDS1.87@545.64,3631.15
NetC26_1: C26.1 C27.1 IC5.3 R34.1 XDS1.9 | length 425.8
  Top Layer w8: XDS1.9@529.89,3024.85 529.89,2972.11 580.4,2921.6 R34.1@580.4,2913.26 C26.1@638,2913.26 C27.1@695,2913.26 825.74,2913.26 838.79,2900.21 IC5.3@838.79,2870.75
NetC28_1: C28.1 R35.1 XDS1.68 | length 340.6
  Top Layer w8: XDS1.68@844.85,3631.15 844.85,3600.15 854,3591 944,3591 1031,3678 C28.1@1062.38,3678 1062.38,3729.38 R35.1@1061.76,3730
NetC29_1: C29.1 XDS1.88 Y3.3 | length 227.2
  Top Layer w8: XDS1.88@529.89,3631.15 529.89,3664.05 553,3687.16 553,3734.17 593.33,3774.5 Y3.3@598.31,3774.5 598.31,3826.66 C29.1@598,3826.97
NetC30_1: C30.1 XDS1.89 Y3.1 | length 140.7
  Top Layer w8: C30.1@452.72,3712.38 453.6,3711.5 Y3.1@511.69,3711.5 514.14,3709.06 XDS1.89@514.14,3631.15
NetC34_1: C34.1 R43.1 R44.2 XDS2.6 | length 250.2
  Top Layer w8: R43.1@1428.38,3326 1428.38,3331.76 R44.2@1475.62,3379 C34.1@1475.62,3432 1475.62,3446.62 1544.2,3515.2 XDS2.6@1544.2,3528.2
NetC48_1: C48.1 R75.2 R76.1 | length 161.2
  Top Layer w10: R76.1@1250,2081.5 1250,2158.5 R75.2@1240,2168.5 1282.73,2168.5 C48.1@1310,2168.5
NetC49_1: C49.1 R77.2 R78.1 | length 157.4
  Top Layer w10: R77.2@1100,2168.5 1139,2168.5 ; R78.1@1140,2081.5 1140,2167.5 1139,2168.5 ; C49.1@1170,2168.5 1139,2168.5
NetC50_1: C50.1 R79.2 R80.1 | length 170.8
  Top Layer w10: R79.2@820,2168.5 859,2168.5 ; 860,2167.5 859,2168.5 ; R80.1@920,2081.5 920,2138.5 C50.1@890,2168.5 859,2168.5
NetC51_1: C51.1 R81.2 R82.1 | length 156.3
  Top Layer w10: R82.1@1379.84,2082.25 1379.84,2168.34 R81.2@1380,2168.5 C51.1@1450,2168.5
NetC52_1: C52.1 R83.2 R84.1 | length 157
  Top Layer w10: R83.2@960,2168.5 C52.1@1030,2168.5 R84.1@1030,2081.5
NetC54_1: C54.1 IC3.1 R90.2 USB2.6 USB2.7 USB2.8 USB2.9 USB2.10 USB2.11 | length 1198.2
  Top Layer w8: v1(250,3843) 357.14,3843 IC3.1@407.32,3893.17
  Top Layer w16: USB2.10@294.58,4103 294.58,4071.01 USB2.11@353.14,4012.45 353.14,4028.5 405,4080.35 405,4094.82 USB2.9@413.18,4103 USB2.8@487,4103 487,4085.31 547.04,4025.27 USB2.6@547.04,4012.45 ; USB2.7@605.6,4103 605.6,4071.01 USB2.6@547.04,4012.45 ; C54.1@680.76,4060 R90.2@680.76,3994 565.49,3994 USB2.6@547.04,4012.45
  Bottom Layer w8: v1(250,3843) 250,4058.42 USB2.10@294.58,4103
NetD2_1: D2.1 D2.2 R47.1 T2.1 | length 234.7
  Top Layer w12: R47.1@1930.62,3791 1997.14,3791 D2.2@1997.6,3790.54 ; T2.1@1996.6,3674.59 1997.6,3675.59 D2.2@1997.6,3790.54 ; D2.1@1997.6,3841.72 D2.2@1997.6,3790.54
NetD2_3: D2.3 R48.1 T1.1 T2.3 | length 343.5
  Top Layer w8: D2.3@2072.4,3816.13 2072.4,3727 ; T1.1@2154,3649 T2.3@2071.4,3649 2072.4,3650 2072.4,3727 ; R48.1@2165.38,3726 2073.4,3726 2072.4,3727
NetD3_3: D3.3 L1.1 T1.3 | length 318.9
  Top Layer w24: L1.1@2228.8,3494.06 2228.8,3558 T1.3@2228.8,3623.41
  Top Layer w25: D3.3@2071.4,3493 2071.4,3499.33 2130.07,3558 2228.8,3558 ; L1.1@2227.74,3493 L1.1@2228.8,3494.06
NetJ1/J3_3: J1/J3.3 J14.2 | length 455.5
  Bottom Layer w8: J1/J3.3@250,1950 292.39,1992.39 510.15,1992.39 553.54,1949 J14.2@670,1949
NetJ1/J3_26: J1/J3.26 R58.1 | length 288.1
  Top Layer w10: J1/J3.26@350,1650 376.8,1676.8 R58.1@627,1676.8
NetJ1/J3_29: J1/J3.29 J15.2 | length 320
  Bottom Layer w8: J1/J3.29@350,1350 J15.2@670,1350
NetJ4_2: J4.2 R4.1 | length 112.6
  Top Layer w8: R4.1@1157.38,437.26 1157.38,516.24 J4.2@1181.14,540
NetJ5_2: J5.2 R5.1 | length 104.1
  Top Layer w8: R5.1@790.16,448.05 790.16,510.78 J5.2@819.38,540
NetJ6_2: J6.2 R6.1 | length 117.8
  Top Layer w8: R6.1@857,448 857,477.62 J6.2@919.38,540
NetJ7_2: J7.2 R7.1 | length 133.2
  Top Layer w8: R7.1@924,448.62 928,448.62 J7.2@1019.38,540
NetJ8_2: J8.2 R14.2 S1.3 | length 230.6
  Top Layer w10: S1.3@134.34,2517.4 147.91,2517.4 246.35,2418.97 J8.2@324.12,2418.97
NetJ9_2: J9.2 R56.1 RT1.2 | length 273.6
  Top Layer w8: J9.2@370,950 534.71,950 R56.1@551,966.29 550,967.29 RT1.2@550,1051.7
NetJ9_3: J9.3 R57.2 | length 295.6
  Top Layer w8: J9.3@370,850 407,850 492.5,935.5 626.67,935.5 R57.2@629.17,933
NetJ19_1: J19.1 R18.1 | length 159.9
  Top Layer w10: R18.1@1295,758.5 1394.88,658.62 J19.1@1394.88,640
NetJ19_3: J19.3 R12.1 | length 112.6
  Top Layer w10: R12.1@1347.5,347 1347.5,392.63 J19.3@1394.88,440
NetJ20_1: J20.1 R21.1 | length 159.1
  Top Layer w10: J20.1@1494.88,640 1494.88,660.37 R21.1@1593,758.5
NetJ20_3: J20.3 R16.1 | length 112.5
  Top Layer w10: J20.3@1494.88,440 1541.99,392.88 R16.1@1541.99,347
NetLED1_2: LED1.2 R4.2 | length 82
  Top Layer w8: LED1.2@1159.26,374 1204.62,419.36 R4.2@1204.62,437.26
NetLED2_4: LED2.4 R5.2 | length 533.2
  Top Layer w8: R5.2@790.16,400.81 790.16,324.84 796,319 1069.36,319 1093,342.64 1093,423 1065.46,450.54 LED2.4@1042.57,450.54
NetLED2_5: LED2.5 R6.2 | length 386.4
  Top Layer w8: R6.2@857,400.76 857,339.49 861.62,334.87 1060.87,334.87 1077,351 1077,409.52 1064.52,422 LED2.5@1045.53,422 LED2.5@1046.53,421
NetLED2_6: LED2.6 R7.2 | length 237.9
  Top Layer w8: R7.2@924,401.38 924,356.38 928.38,352 1053.76,352 1061.76,360 1061.76,388.94 1057.24,393.46 LED2.6@1042.57,393.46
NetLED101_1: LED101.1 R29.1 | length 78.9
  Top Layer w8: LED101.1@136.65,2815.41 137.06,2815 R29.1@215.38,2815
NetLED102_1: LED102.1 R30.1 | length 79.9
  Top Layer w8: LED102.1@135.53,2734 R30.1@215.38,2734
NetR24_1: R24.1 XDS1.63 | length 140.4
  Top Layer w8: XDS1.63@951.15,3556.35 983.15,3556.35 1052.8,3626 R24.1@1062.75,3626
NetR25_1: R25.1 XDS1.62 | length 125.4
  Top Layer w8: XDS1.62@951.15,3540.6 1029.35,3540.6 R25.1@1062.75,3574
NetR26_1: R26.1 XDS1.61 | length 112.4
  Top Layer w8: XDS1.61@951.15,3524.85 1059.53,3524.85 R26.1@1062.38,3522
NetR27_1: R27.1 XDS1.60 | length 127.8
  Top Layer w8: XDS1.60@951.15,3509.1 1023.65,3509.1 R27.1@1062.75,3470
NetR29_2: R29.2 XDS1.3 | length 282.2
  Top Layer w8: R29.2@262.62,2815 263.91,2815 435.4,2986.5 XDS1.3@435.4,3024.85
NetR30_2: R30.2 XDS1.4 | length 404.9
  Top Layer w8: R30.2@262.62,2734 324,2734 363.31,2773.31 363.31,2874.31 451.15,2962.15 XDS1.4@451.15,3024.85
NetR32_2: R32.2 XDS1.59 | length 142.4
  Top Layer w8: XDS1.59@951.15,3493.35 987.02,3493.35 R32.2@1062.38,3418
NetR52_2: R52.2 T2.2 | length 71.4
  Top Layer w8: R52.2@1938.5,3655.41 1970.5,3623.41 T2.2@1996.6,3623.41
NetR68_2: R68.2 R69.1 U2.6 | length 172.4
  Top Layer w15: U2.6@426.01,463.99 426.84,463.99 456.84,433.99 R68.2@516.01,433.99 R69.1@516.01,503.99
NetR69_2: R69.2 R72.1 U2.7 | length 210.9
  Top Layer w15: U2.7@426.01,513.99 456.01,513.99 R72.1@516.01,573.99 579,511 R69.2@579,503.99
NetR70_2: R70.2 R71.1 U2.2 | length 165.1
  Top Layer w15: R70.2@130.01,457.99 R71.1@130.01,527.99 205.32,527.99 U2.2@219.32,513.99
NetR71_2: R71.2 R73.1 U2.1 | length 283.3
  Top Layer w15: R71.2@67.02,527.99 103.02,563.99 U2.1@219.32,563.99 277.51,622.19 R73.1@277.51,655.99
NetR73_2: R73.2 U2.5 | length 277.9
  Top Layer w15: R73.2@340.5,655.99 340.5,498.66 425.18,413.99 U2.5@426.01,413.99
NetR86_1: R86.1 USB2.5 | length 221.3
  Top Layer w16: USB2.5@501.27,3998.28 502.13,3997.42 502.13,3956.8 545.97,3912.96 R86.1@663.44,3912.96
NetR89_1: R89.1 USB2.1 | length 203.5
  Top Layer w16: USB2.1@398.05,3997.42 USB2.1@398.91,3998.28
  Top Layer w20: R89.1@260,3899.23 338,3899.23 398.91,3960.14 USB2.1@398.91,3998.28
PA0: J4.1 MSP1.33 R13.1 | length 1034
  Top Layer w8: v1(1040,1340.07) 1073.52,1373.59 MSP1.33@1087.36,1373.59 ; v1(1144.69,820.5) 1181.14,784.05 ; J4.1@1181.14,640 1181.14,784.05 ; R13.1@1348,830 1314.5,796.5 1193.84,796.5 1193.72,796.62 1181.14,784.05
  VCC Layer w8: v1(1040,1340.07) 1040,1333.33 1005.87,1299.2 1005.87,959.31 v1(1144.69,820.5)
PA0-: J19.2 J27.9 R13.2 | length 1391.1
  Top Layer w8: J19.2@1394.88,540 1437.13,582.25 1437.13,788.12 R13.2@1395.24,830
  GND Layer w8: J27.9@550,150 672,272 1229,272 1313,356 1313,458.12 J19.2@1394.88,540
PA1: MSP1.34 R19.1 | length 1278.6
  Top Layer w8: v1(999.96,1333.33) 999.96,1349.91 1065.04,1414.99 1078.33,1414.99 1078.57,1415.23 1100.26,1415.23 1107.05,1408.44 MSP1.34@1107.05,1373.59 ; v1(1220,820.5) 1279.5,880 1518,880 1539.62,858.38 R19.1@1539.62,830.5
  VCC Layer w8: v1(999.96,1333.33) 990,1323.36 990,919 1112.5,796.5 1154.63,796.5 1154.75,796.62 1196.12,796.62 v1(1220,820.5)
PA1-: J20.2 J28.9 R19.2 | length 991.2
  Top Layer w8: R19.2@1492.38,830.5 1452,790.12 1452,582.88 J20.2@1494.88,540
  GND Layer w8: J28.9@1050,150 1107,207 1264,207 1447,390 1447,492.12 J20.2@1494.88,540
PA2-: J28.1 R9.1 | length 1579
  Top Layer w8: R9.1@1669.62,1541 1658.83,1530.2 1658.83,1461.99 1699.39,1421.43 v1(1699.39,1409)
  VCC Layer w8: v1(1653.02,326.02) 1653.02,1362.63 v1(1699.39,1409)
  Bottom Layer w8: J28.1@1470,170 J28.1@1450,150 1450.8,150 1497.8,197 1557,197 1653.02,293.02 v1(1653.02,326.02)
PA2_ROSC: MSP1.42 R8.1 R9.2 | length 512.1
  Top Layer w8: MSP1.42@1264.53,1373.59 1264.53,1408.53 1280,1424 v1(1310,1424) ; R9.2@1622.38,1541 1607,1525.62 v1(1607,1503) 1607,1489 1621,1475 R8.1@1637.82,1475 R8.1@1638.38,1475
  VCC Layer w8: v1(1310,1424) 1349,1424 1411,1486 1590,1486 v1(1607,1503)
PA3-: J28.2 R10.1 | length 1151.8
  Top Layer w8: v1(1253.03,1017) 1253.03,1060.64 1252.65,1061.02 R10.1@1260.62,1069
  VCC Layer w8: v1(1253.03,1017) 1253.03,236.45 1252.65,236.06 1294.35,194.35 1294.35,124.65 1319,100 1400,100 J28.2@1450,50
PA3_LFXIN: C9.2 MSP1.43 R10.2 Y1.2 | length 390.3
  Top Layer w8: v1(1181.65,1158) C9.2@1214.38,1158 ; v1(1182,1082) 1200.38,1082 R10.2@1213.38,1069 ; C9.2@1208.26,1158.65 ccw(c1155.34,1231) Y1.2@1244.98,1231 1284.21,1270.23 MSP1.43@1284.21,1373.59 MSP1.43@1285.4,1372.4
  Bottom Layer w8: v1(1181.65,1158) 1182,1157.65 v1(1182,1082)
PA4-: J28.3 R11.1 | length 935.8
  Top Layer w8: v1(1322.9,1019) 1322.9,1068.27 R11.1@1324.38,1069.75
  VCC Layer w8: v1(1322.9,1019) 1322.9,974.48 1350,947.38 J28.3@1350,150
  Bottom Layer w8: J28.3@1347,153 J28.3@1350,150
PA4_LFXOUT: C11.2 MSP1.44 R11.2 Y1.1 | length 330.5
  Top Layer w8: MSP1.44@1303.9,1373.59 1303.9,1270.51 Y1.1@1343.4,1231 ccw(c1434.2,1231) C11.2@1378.31,1159.45 ; C11.2@1370.96,1158.65 1370.96,1070.41 R11.2@1371.62,1069.75
PA5-: J28.4 R15.1 | length 1351.7
  Top Layer w8: J28.4@1350,50 1304,96 1225.58,96 1199,122.58 1199,222 1109.62,311.38 1109.62,827.19 1195.43,913 1420.58,913 1430,922.42 R15.1@1430,991.63
PA5_HFXIN: C10.2 MSP1.45 R15.2 Y2.3 | length 394.5
  Top Layer w8: MSP1.45@1323.58,1373.59 1323.58,1320.29 1393,1250.88 1393,1234.33 1446.82,1180.5 1448.05,1180.5 1436.38,1168.83 C10.2@1436.38,1105 1436.38,1045.25 R15.2@1430,1038.87
PA6-: J28.5 R17.1 | length 1262.3
  Top Layer w8: J28.5@1250,150 v1(1398,298) ; v1(1456,961) 1456,993 1556.25,1093.25 1626.75,1093.25 1676.38,1142.88 R17.1@1676.38,1194.38
  VCC Layer w8: v1(1398,298) 1455.35,355.35 1455.35,960.35 v1(1456,961)
PA6_HFXOUT: C12.2 MSP1.46 R17.2 Y2.1 | length 416.4
  Top Layer w8: MSP1.46@1343.27,1373.59 1343.27,1324.73 1372.88,1295.12 1483.04,1295.12 1534.66,1243.5 1674.5,1243.5 R17.2@1676.38,1241.62
PA7_CLK-OUT: J28.6 MSP1.49 | length 1682.5
  Top Layer w8: MSP1.49@1459.41,1450.36 1459.41,1430.59 v1(1470,1420)
  VCC Layer w8: v1(1470,1420) 1580,1310 v1(1580,299)
  Bottom Layer w8: J28.6@1250,50 1300,100 1300,182 1328,210 1491,210 v1(1580,299)
PA8_UART1-TX: J1/J3.4 MSP1.54 | length 1463.6
  Top Layer w8: v1(1334.84,1559.36) 1367.56,1559.36 1378.12,1548.79 MSP1.54@1459.41,1548.79
  Bottom Layer w8: J1/J3.4@250,1850 299,1801 943.19,1801 977.23,1766.97 977.23,1611.32 1075.32,1513.23 1135.02,1513.23 1181.14,1559.36 v1(1334.84,1559.36)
